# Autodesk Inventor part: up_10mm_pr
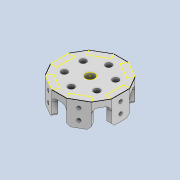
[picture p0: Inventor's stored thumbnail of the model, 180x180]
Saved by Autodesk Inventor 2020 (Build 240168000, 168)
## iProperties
Created: 2021-10
Part Number: up_10mm_pr
Material: Generic
Document SubType Name: Modeling
Designer: Shuang Peng
Density: 1 g/cm^3
Appearance: Default
Author: Shuang Peng
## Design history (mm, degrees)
sketch "Sketch1"
  geometry: C1 r 1.5 at (0, 0); 1 further point
  constraints: 1 centre point, 1 coincident
  dimensions: "d0" = 3 diameter of C1
extrude "Extrusion1" new body sketch "Sketch1" distance "d1" = 5; taper "d2" = 0 deg
sketch "Sketch2"
  geometry: L1 (0, 0)-(-10, 0); L2 (-10, 0)-(-9, 0); L3 (-8, -3)-(-10, -3); L4 (-10, -3)-(-10, 3); L5 (-10, 3)-(-8, 3); L6 (-8, 3)-(-8, -3); L7 (-8, -3)-(-10, 3); L8 (-10, -3)-(-8, 3)
  constraints: 16 end point, 2 horizontal, 2 midpoint, 2 parallel, 1 perpendicular, 1 point on line
  dimensions: "d3" = 10 distance of L1.start L1.end; "d4" = 1 distance of L1.end L2.end; "d5" = 2 distance of L3.start L3.end; "d6" = 6 distance of L3.end L4.end
extrude "Extrusion2" join sketch "Sketch2" stored distance "d7" = 5; taper "d8" = 0 deg
pattern_circular "Circular Pattern1" dims angle "d10" = 360 deg
extrude "Extrusion4" join sketch "Sketch4" distance "d19" = 2; taper "d20" = 0 deg
sketch "Sketch5"
  geometry: L1 (6, 0)-(0, 0) reference; L2 (0, 0)-(0, -2) reference; L3 (0, -2)-(6, -2) reference; L4 (6, -2)-(6, 0) reference; L5 (13.16, -7.598)-(10.16, -2.402) reference; L6 (10.16, -2.402)-(8.428, -3.402) reference; L7 (8.428, -3.402)-(11.428, -8.598) reference; L8 (11.428, -8.598)-(13.16, -7.598) reference; L9 (10.16, -17.598)-(13.16, -12.402) reference; L10 (13.16, -12.402)-(11.428, -11.402) reference; L11 (11.428, -11.402)-(8.428, -16.598) reference; L12 (8.428, -16.598)-(10.16, -17.598) reference; L13 (0, -20)-(6, -20) reference; L14 (6, -20)-(6, -18) reference; L15 (6, -18)-(0, -18) reference; L16 (0, -18)-(0, -20) reference; L17 (-7.16, -12.402)-(-4.16, -17.598) reference; L18 (-4.16, -17.598)-(-2.428, -16.598) reference; L19 (-2.428, -16.598)-(-5.428, -11.402) reference; L20 (-5.428, -11.402)-(-7.16, -12.402) reference; L21 (-4.16, -2.402)-(-7.16, -7.598) reference; L22 (-7.16, -7.598)-(-5.428, -8.598) reference; L23 (-5.428, -8.598)-(-2.428, -3.402) reference; L24 (-2.428, -3.402)-(-4.16, -2.402) reference; 1 further point
extrude "Extrusion5" join sketch "Sketch5" distance "d21" = 3; taper "d22" = 0 deg
sketch "Sketch6"
  geometry: L1 (0, 0)-(0, -6) reference; L2 (0, 2)-(0, 0) reference; L3 (-6, 2)-(0, 2) reference; L4 (-6, 2)-(-6, 0) reference; L5 (-6, 0)-(-6, -6) reference; L6 (0, -6)-(-6, -6) reference; L7 (-3, 2)-(-3, -6); L8 (-6, -6)-(0, -6) reference; L9 (-3, -2)-(-3, -3.75); L10 (-3, -2)-(-3, -0.25); C1 r 0.55 at (-3, -3.75); C2 r 0.55 at (-3, -0.25); 1 further point
  constraints: 6 end point, 3 midpoint, 2 centre point, 2 coincident, 2 point on line
  dimensions: "d23" = 1.75 distance of L9.start L9.end; "d24" = 1.75 distance of L9.start L10.end; "d25" = 1.1 diameter of C1; "d26" = 1.1 diameter of C2
extrude "Extrusion6" cut sketch "Sketch6" distance "d27" = 5; taper "d28" = 0 deg
pattern_circular "Circular Pattern3" dims angle "d30" = 360 deg
sketch "Sketch7"
  geometry: L1 (9.683, -14.424)-(7.085, -12.924) reference; L2 (7.085, -12.924)-(7.575, -12.076) reference; L3 (7.575, -12.076)-(10.173, -13.576) reference; L4 (11.428, -11.402)-(10.173, -13.576) reference; L5 (13.16, -12.402)-(11.428, -11.402) reference; L6 (13.16, -12.402)-(13.16, -7.598) reference; L7 (11.428, -8.598)-(13.16, -7.598) reference; L8 (10.173, -6.424)-(11.428, -8.598) reference; L9 (10.173, -6.424)-(7.575, -7.924) reference; L10 (7.575, -7.924)-(7.085, -7.076) reference; L11 (7.085, -7.076)-(9.683, -5.576) reference; L12 (8.428, -3.402)-(9.683, -5.576) reference; L13 (10.16, -2.402)-(8.428, -3.402) reference; L14 (10.16, -2.402)-(6, 0) reference; L15 (6, -2)-(6, 0) reference; L16 (3.49, -2)-(6, -2) reference; L17 (3.49, -2)-(3.49, -5) reference; L18 (3.49, -5)-(2.51, -5) reference; L19 (2.51, -5)-(2.51, -2) reference; L20 (0, -2)-(2.51, -2) reference; L21 (0, 0)-(0, -2) reference; L22 (0, 0)-(-4.16, -2.402) reference; L23 (-2.428, -3.402)-(-4.16, -2.402) reference; L24 (-3.683, -5.576)-(-2.428, -3.402) reference; L25 (-3.683, -5.576)-(-1.085, -7.076) reference; L26 (-1.085, -7.076)-(-1.575, -7.924) reference; L27 (-1.575, -7.924)-(-4.173, -6.424) reference; L28 (-5.428, -8.598)-(-4.173, -6.424) reference; L29 (-7.16, -7.598)-(-5.428, -8.598) reference; L30 (-7.16, -7.598)-(-7.16, -12.402) reference; L31 (-5.428, -11.402)-(-7.16, -12.402) reference; L32 (-4.173, -13.576)-(-5.428, -11.402) reference; L33 (-4.173, -13.576)-(-1.575, -12.076) reference; L34 (-1.575, -12.076)-(-1.085, -12.924) reference; L35 (-1.085, -12.924)-(-3.683, -14.424) reference; L36 (-2.428, -16.598)-(-3.683, -14.424) reference; L37 (-4.16, -17.598)-(-2.428, -16.598) reference; L38 (-4.16, -17.598)-(0, -20) reference; L39 (0, -18)-(0, -20) reference; L40 (2.51, -18)-(0, -18) reference; L41 (2.51, -18)-(2.51, -15) reference; L42 (2.51, -15)-(3.49, -15) reference; L43 (3.49, -15)-(3.49, -18) reference; L44 (6, -18)-(3.49, -18) reference; L45 (6, -20)-(6, -18) reference; L46 (6, -20)-(10.16, -17.598) reference; L47 (8.428, -16.598)-(10.16, -17.598) reference; L48 (9.683, -14.424)-(8.428, -16.598) reference; C1 r 1.5 at (3, -10) reference; C2 r 1.5 at (3, -10) reference; C3 r 3 at (3, -10); 1 further point
  constraints: 1 centre point, 1 coincident
  dimensions: "d32" = 6 diameter of C3
extrude "Extrusion7" join sketch "Sketch7" stored distance "d33" = 5; taper "d34" = 0 deg
sketch "Sketch8"
  geometry: C1 r 1.5 at (0, 0); 1 further point
  constraints: 1 centre point, 1 coincident
  dimensions: "d35" = 3 diameter of C1
extrude "Extrusion8" cut sketch "Sketch8" distance "d36" = 5; taper "d37" = 0 deg
fillet "Fillet1" dims "d38" = 1.5
pattern_circular "Circular Pattern4" dims angle "d40" = 360 deg
fillet "Fillet2" dims "d42" = 0.5
pattern_circular "Circular Pattern5" dims angle "d44" = 360 deg
chamfer "Chamfer1" distance "d46" = 1; stored, may be unused: second distance "d47" = 2, angle "d48" = 45 deg
fillet "Fillet3" dims "d49" = 1
sketch "Sketch9"
  geometry: L1 (-1.33, -2.5)-(2.51, -2.5) reference; L2 (-3.25, -5.826)-(-1.33, -2.5) reference; L3 (-3.25, -5.826)-(-1.085, -7.076) reference; L4 (-1.085, -7.076)-(-1.575, -7.924) reference; L5 (-1.575, -7.924)-(-3.74, -6.674) reference; L6 (-5.66, -10)-(-3.74, -6.674) reference; L7 (-3.74, -13.326)-(-5.66, -10) reference; L8 (-3.74, -13.326)-(-1.575, -12.076) reference; L9 (-1.575, -12.076)-(-1.085, -12.924) reference; L10 (-1.085, -12.924)-(-3.25, -14.174) reference; L11 (-1.33, -17.5)-(-3.25, -14.174) reference; L12 (2.51, -17.5)-(-1.33, -17.5) reference; L13 (2.51, -17.5)-(2.51, -15) reference; L14 (2.51, -15)-(3.49, -15) reference; L15 (3.49, -15)-(3.49, -17.5) reference; L16 (7.33, -17.5)-(3.49, -17.5) reference; L17 (9.25, -14.174)-(7.33, -17.5) reference; L18 (9.25, -14.174)-(7.085, -12.924) reference; L19 (7.085, -12.924)-(7.575, -12.076) reference; L20 (7.575, -12.076)-(9.74, -13.326) reference; L21 (11.66, -10)-(9.74, -13.326) reference; L22 (9.74, -6.674)-(11.66, -10) reference; L23 (9.74, -6.674)-(7.575, -7.924) reference; L24 (7.575, -7.924)-(7.085, -7.076) reference; L25 (7.085, -7.076)-(9.25, -5.826) reference; L26 (7.33, -2.5)-(9.25, -5.826) reference; L27 (3.49, -2.5)-(7.33, -2.5) reference; L28 (3.49, -2.5)-(3.49, -5) reference; L29 (3.49, -5)-(2.51, -5) reference; L30 (2.51, -5)-(2.51, -2.5) reference; L31 (3, -10)-(-1.33, -17.5); L32 (-1.33, -17.5)-(-0.08, -15.335); C1 r 4 at (3, -10) reference; C2 r 1 at (-0.08, -15.335); 1 further point
  constraints: 4 end point, 1 centre point, 1 coincident, 1 point on line
  dimensions: "d50" = 2.5 distance of L11.start L32.end; "d51" = 2 diameter of C2
extrude "Extrusion9" cut sketch "Sketch9" distance "d52" = 5; taper "d53" = 0 deg
pattern_circular "Circular Pattern6" dims angle "d55" = 360 deg
thicken "Thicken1" dims "d57" = 0.5, "d58" = 0.5
thicken "Thicken2" dims "d59" = 0.5, "d60" = 0.5
thicken "Thicken3" dims "d61" = 0.5, "d62" = 0.5
thicken "Thicken4" dims "d63" = 0.5, "d64" = 0.5
thicken "Thicken5" dims "d65" = 0.5, "d66" = 0.5
thicken "Thicken6" dims "d67" = 0.5, "d68" = 0.5
body "Solid1"
node "Projected Loop9"
node "Projected Loop10"
node "Projected Loop11"
node "Projected Loop12"
node "Projected Loop13"
node "Projected Loop14"
node "Projected Loop15"
node "Projected Loop16"
node "Projected Loop17"
